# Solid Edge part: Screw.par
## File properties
Title: Screw
Author: Robert a Rhodes jr
Template: Normal.par
Last saved by: CADCIM
Revision: 9
Application: Solid Edge
Material: aluminum
Accuracy: 0.99
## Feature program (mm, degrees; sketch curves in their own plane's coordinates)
sketch for "unnamed Protrusion 1" plane through (0, 0, 0) normal (0, -1, 0) x-axis (1, 0, 0)
  circle centre (0, 0) radius 12.5
extrude "unnamed Protrusion 1" add finite 25 along +normal
sketch for "ExtrudedProtrusion_2" plane through (0, -25, 0) normal (0, -1, 0) x-axis (1, 0, 0)
  circle centre (0, 0) radius 10
extrude "ExtrudedProtrusion_2" add finite 96 along +normal
sketch for "ExtrudedProtrusion_3" plane through (0, -121, 0) normal (0, -1, 0) x-axis (1, 0, 0)
  circle centre (0, 0) radius 6
extrude "ExtrudedProtrusion_3" add finite 4 along +normal
sketch for "ExtrudedProtrusion_4" plane through (0, -125, 0) normal (0, -1, 0) x-axis (1, 0, 0)
  circle centre (0, 0) radius 4
extrude "ExtrudedProtrusion_4" add finite 6 along +normal
sketch for "unnamed RevolvedProtrusion 1" plane through (0, 0, 0) normal (0, 0, 1) x-axis (1, 0, 0)
  line (0, -131) -> (6, -131)
  line (6, -131) -> (6, -141)
  line (6, -141) -> (0, -143.8522)
  line (0, -143.8522) -> (0, -131)
revolve "unnamed RevolvedProtrusion 1" add full turn 360 deg about sketch line (0, -131) -> (0, -106.3065)
sketch for "ExtrudedCutout_1" plane through (0, 0, 0) normal (1, 0, 0) x-axis (0, 1, 0)
  circle centre (-13, 0) radius 5.5
extrude "ExtrudedCutout_1" cut finite 222.1 symmetric
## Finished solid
Body 1: solid body, 12 faces, 12 edges, 1 vertex.
  Faces by surface: cylinder 6, plane 5, cone 1
  Edges by curve: circle 10, intersection 2
Bounding box of the edges (mm): 25.000 x 141.000 x 25.000, from (-12.5, -141, -12.5) to (12.5, 0, 12.5).
Cylindrical faces by radius (mm): R4 x1, R5.5 x1, R6 x2, R10 x1, R12.5 x1
Conical faces (half-angle, radius in mm at the cone's reference point): 64.5754 deg R6 x1
Planar faces by outward normal: +y 2, -y 3
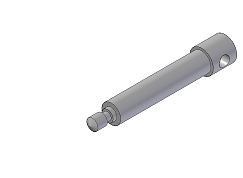
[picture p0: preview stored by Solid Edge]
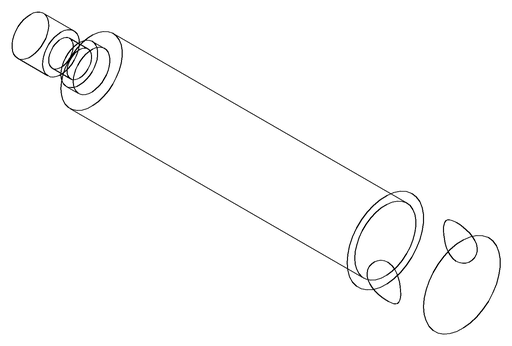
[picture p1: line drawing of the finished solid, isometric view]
